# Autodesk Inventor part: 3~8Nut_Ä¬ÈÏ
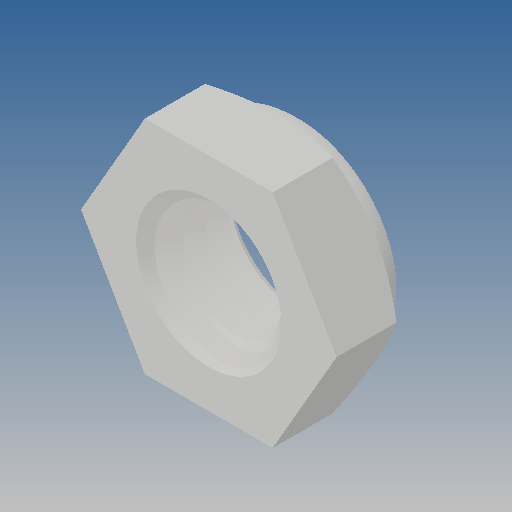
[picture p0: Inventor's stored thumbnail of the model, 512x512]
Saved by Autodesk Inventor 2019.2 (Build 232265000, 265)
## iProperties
Created: 2010-06
Part Number: 3~8Nut_Ä¬ÈÏ
Material: Ogólny
Document SubType Name: Modeling
Designer: CADENGINEERING4
Density: 1 g/cm^3
Appearance: Domyślna
Author: CADENGINEERING4
Revision Number: ÈÎºÎ
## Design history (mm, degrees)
feature "NONE"
node "Bryła1"
